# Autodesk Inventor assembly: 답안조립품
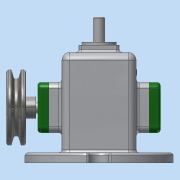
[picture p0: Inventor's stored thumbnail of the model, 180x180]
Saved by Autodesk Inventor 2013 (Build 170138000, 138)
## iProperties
Created: 2018-07
Part Number: 답안조립품
Document SubType Name: Assembly
Designer: Administrator
Author: Administrator
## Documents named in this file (16)
- C:\Users\Administrator\Desktop\480708V1011\답안조립품.iam
- C:\Users\Administrator\Desktop\480708V1011\본체.ipt
- C:\Users\Administrator\Desktop\480708V1011\앞커버.ipt
- C:\Users\Administrator\Desktop\480708V1011\뒤커버.ipt
- C:\Users\Administrator\Desktop\480708V1011\베어링 12x32x10.ipt
- C:\Users\Administrator\Desktop\480708V1011\편심축.ipt
- C:\Users\Administrator\Desktop\480708V1011\오일 실 12 25 7.ipt
- C:\Users\Administrator\Desktop\480708V1011\볼트 M4.ipt
- C:\Users\Administrator\Desktop\480708V1011\키 4x4x10.ipt
- C:\Users\Administrator\Desktop\480708V1011\V벨트풀리.ipt
- C:\Users\Administrator\Desktop\480708V1011\멈춤나사 M3x8.ipt
- C:\Users\Administrator\Desktop\480708V1011\링크.ipt
- C:\Users\Administrator\Desktop\480708V1011\슬라이드.ipt
- C:\Users\Administrator\Desktop\480708V1011\핀 5x18.ipt
- C:\Users\Administrator\Desktop\480708V1011\고정핀 1.2x8.ipt
- C:\Users\Administrator\Desktop\480708V1011\부시.ipt
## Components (3 placed, 3 different names)
1. V벨트풀리:1 — 각도:2
2. 핀 5x18:1
3. 고정핀 1.2x8:1
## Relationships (1: Angle 1)
- 각도:2 [Angle]: V벨트풀리:1
